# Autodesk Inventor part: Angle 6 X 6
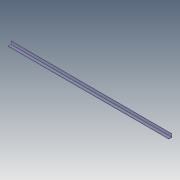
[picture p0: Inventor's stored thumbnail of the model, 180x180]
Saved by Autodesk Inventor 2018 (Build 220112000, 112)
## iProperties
Created: 2018-02
Part Number: Angle 6 X 6
Material: Steel, Mild
Document SubType Name: Modeling
Designer: STK
Density: 7.85 g/cm^3
Appearance: Slate Blue
Author: STK
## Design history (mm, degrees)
sketch "Sketch1"
  geometry: L1 (11.794, 11.987)-(11.794, 164.387); L2 (21.319, 150.917)-(21.319, 35.8); L3 (150.723, 21.512)-(35.606, 21.512); L4 (164.194, 11.987)-(11.794, 11.987); A1 r 14.287 centre (7.031, 150.917) between (21.319, 150.917) and (11.794, 164.387); A2 r 14.287 centre (35.606, 35.8) between (21.319, 35.8) and (35.606, 21.512); A3 r 14.287 centre (150.723, 7.225) between (164.194, 11.987) and (150.723, 21.512)
  constraints: 8 end point, 6 point on circle, 4 tangent, 3 centre point, 2 equal radius, 1 parallel, 1 perpendicular
  dimensions: "d5" = 14.2875 radius of A2 (derived); "d6" = 152.4 distance from line of L1.end L4 (= d3); "d3" = 152.4 distance from line of L4.start L1 (derived); "d1" = 9.525 distance between parallel lines of L3 L4 (derived); "d0" = 9.525 distance between parallel lines of L2 L1 (= d1)
feature "Angle_equal:1" sketch "Sketch1"
workplane "Work Plane1"
body "Solid1"
